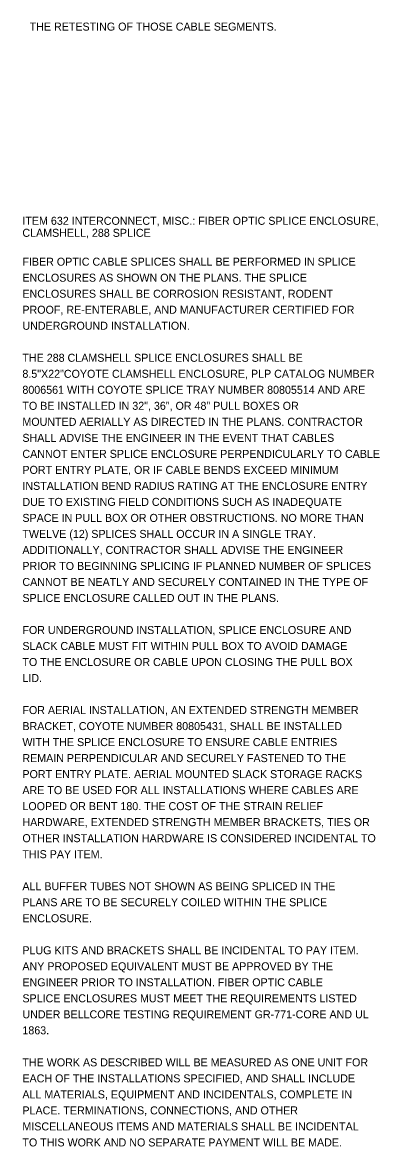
# Model space of a CAD drawing. Extents: x -39 to 75, y -25 to 14.
# Drawn here: x -26.72 to -20.47, y -25.2 to -5.55 of the extents above; entities that cross this region are included whole.
import ezdxf

# ---------------------------------------------------------------- set-up
doc = ezdxf.new("R2010")
doc.units = 0
doc.layers.add('SH_Text', color=7, linetype='Continuous')

msp = doc.modelspace()

# ---------------------------------------------------------------- texts
at = {"layer": 'SH_Text'}
for s, p in [('THE RETESTING OF THOSE CABLE SEGMENTS.                             ', (-26.597, -5.688)), ('ITEM 632 INTERCONNECT, MISC.: FIBER OPTIC SPLICE ENCLOSURE, ', (-26.724, -9.084)), ('CLAMSHELL, 288 SPLICE ', (-26.724, -9.294)), ('FIBER OPTIC CABLE SPLICES SHALL BE PERFORMED IN SPLICE ', (-26.724, -9.799)), ('ENCLOSURES AS SHOWN ON THE PLANS. THE SPLICE ', (-26.724, -10.079)), ('ENCLOSURES SHALL BE CORROSION RESISTANT, RODENT ', (-26.724, -10.359)), ('PROOF, RE-ENTERABLE, AND MANUFACTURER CERTIFIED FOR ', (-26.724, -10.639)), ('UNDERGROUND INSTALLATION.', (-26.724, -10.919)), ('THE 288 CLAMSHELL SPLICE ENCLOSURES SHALL BE ', (-26.724, -11.479)), ('8.5"X22"COYOTE CLAMSHELL ENCLOSURE, PLP CATALOG NUMBER ', (-26.724, -11.759)), ('8006561 WITH COYOTE SPLICE TRAY NUMBER 80805514 AND ARE ', (-26.724, -12.039)), ('TO BE INSTALLED IN 32", 36", OR 48" PULL BOXES OR ', (-26.724, -12.319)), ('MOUNTED AERIALLY AS DIRECTED IN THE PLANS. CONTRACTOR ', (-26.724, -12.599)), ('SHALL ADVISE THE ENGINEER IN THE EVENT THAT CABLES ', (-26.724, -12.879)), ('CANNOT ENTER SPLICE ENCLOSURE PERPENDICULARLY TO CABLE ', (-26.724, -13.159)), ('PORT ENTRY PLATE, OR IF CABLE BENDS EXCEED MINIMUM ', (-26.724, -13.439)), ('INSTALLATION BEND RADIUS RATING AT THE ENCLOSURE ENTRY ', (-26.724, -13.719)), ('DUE TO EXISTING FIELD CONDITIONS SUCH AS INADEQUATE ', (-26.724, -13.999)), ('SPACE IN PULL BOX OR OTHER OBSTRUCTIONS. NO MORE THAN ', (-26.724, -14.279)), ('TWELVE (12) SPLICES SHALL OCCUR IN A SINGLE TRAY. ', (-26.724, -14.559)), ('ADDITIONALLY, CONTRACTOR SHALL ADVISE THE ENGINEER ', (-26.724, -14.839)), ('PRIOR TO BEGINNING SPLICING IF PLANNED NUMBER OF SPLICES ', (-26.724, -15.119)), ('CANNOT BE NEATLY AND SECURELY CONTAINED IN THE TYPE OF ', (-26.724, -15.399)), ('SPLICE ENCLOSURE CALLED OUT IN THE PLANS.', (-26.724, -15.679)), ('FOR UNDERGROUND INSTALLATION, SPLICE ENCLOSURE AND ', (-26.724, -16.239)), ('SLACK CABLE MUST FIT WITHIN PULL BOX TO AVOID DAMAGE ', (-26.724, -16.519)), ('TO THE ENCLOSURE OR CABLE UPON CLOSING THE PULL BOX ', (-26.724, -16.799)), ('LID.', (-26.724, -17.079)), ('FOR AERIAL INSTALLATION, AN EXTENDED STRENGTH MEMBER ', (-26.724, -17.639)), ('BRACKET, COYOTE NUMBER 80805431, SHALL BE INSTALLED ', (-26.724, -17.919)), ('WITH THE SPLICE ENCLOSURE TO ENSURE CABLE ENTRIES ', (-26.724, -18.199)), ('REMAIN PERPENDICULAR AND SECURELY FASTENED TO THE ', (-26.724, -18.479)), ('PORT ENTRY PLATE. AERIAL MOUNTED SLACK STORAGE RACKS ', (-26.724, -18.759)), ('ARE TO BE USED FOR ALL INSTALLATIONS WHERE CABLES ARE ', (-26.724, -19.039)), ('LOOPED OR BENT 180. THE COST OF THE STRAIN RELIEF ', (-26.724, -19.319)), ('HARDWARE, EXTENDED STRENGTH MEMBER BRACKETS, TIES OR ', (-26.724, -19.599)), ('OTHER INSTALLATION HARDWARE IS CONSIDERED INCIDENTAL TO ', (-26.724, -19.879)), ('THIS PAY ITEM.', (-26.724, -20.159)), ('ALL BUFFER TUBES NOT SHOWN AS BEING SPLICED IN THE ', (-26.724, -20.719)), ('PLANS ARE TO BE SECURELY COILED WITHIN THE SPLICE ', (-26.724, -20.999)), ('ENCLOSURE. ', (-26.724, -21.279)), ('PLUG KITS AND BRACKETS SHALL BE INCIDENTAL TO PAY ITEM.  ', (-26.724, -21.839)), ('ANY PROPOSED EQUIVALENT MUST BE APPROVED BY THE ', (-26.724, -22.119)), ('ENGINEER PRIOR TO INSTALLATION. FIBER OPTIC CABLE ', (-26.724, -22.399)), ('SPLICE ENCLOSURES MUST MEET THE REQUIREMENTS LISTED ', (-26.724, -22.679)), ('UNDER BELLCORE TESTING REQUIREMENT GR-771-CORE AND UL ', (-26.724, -22.959)), ('1863.', (-26.724, -23.239)), ('THE WORK AS DESCRIBED WILL BE MEASURED AS ONE UNIT FOR ', (-26.724, -23.799)), ('EACH OF THE INSTALLATIONS SPECIFIED, AND SHALL INCLUDE ', (-26.724, -24.079)), ('ALL MATERIALS, EQUIPMENT AND INCIDENTALS, COMPLETE IN ', (-26.724, -24.359)), ('PLACE. TERMINATIONS, CONNECTIONS, AND OTHER ', (-26.724, -24.639)), ('MISCELLANEOUS ITEMS AND MATERIALS SHALL BE INCIDENTAL ', (-26.724, -24.919)), ('TO THIS WORK AND NO SEPARATE PAYMENT WILL BE MADE. ', (-26.724, -25.199))]:
    msp.add_text(s, height=0.14, dxfattribs=at).set_placement(p)

doc.saveas('drawing.dxf')
